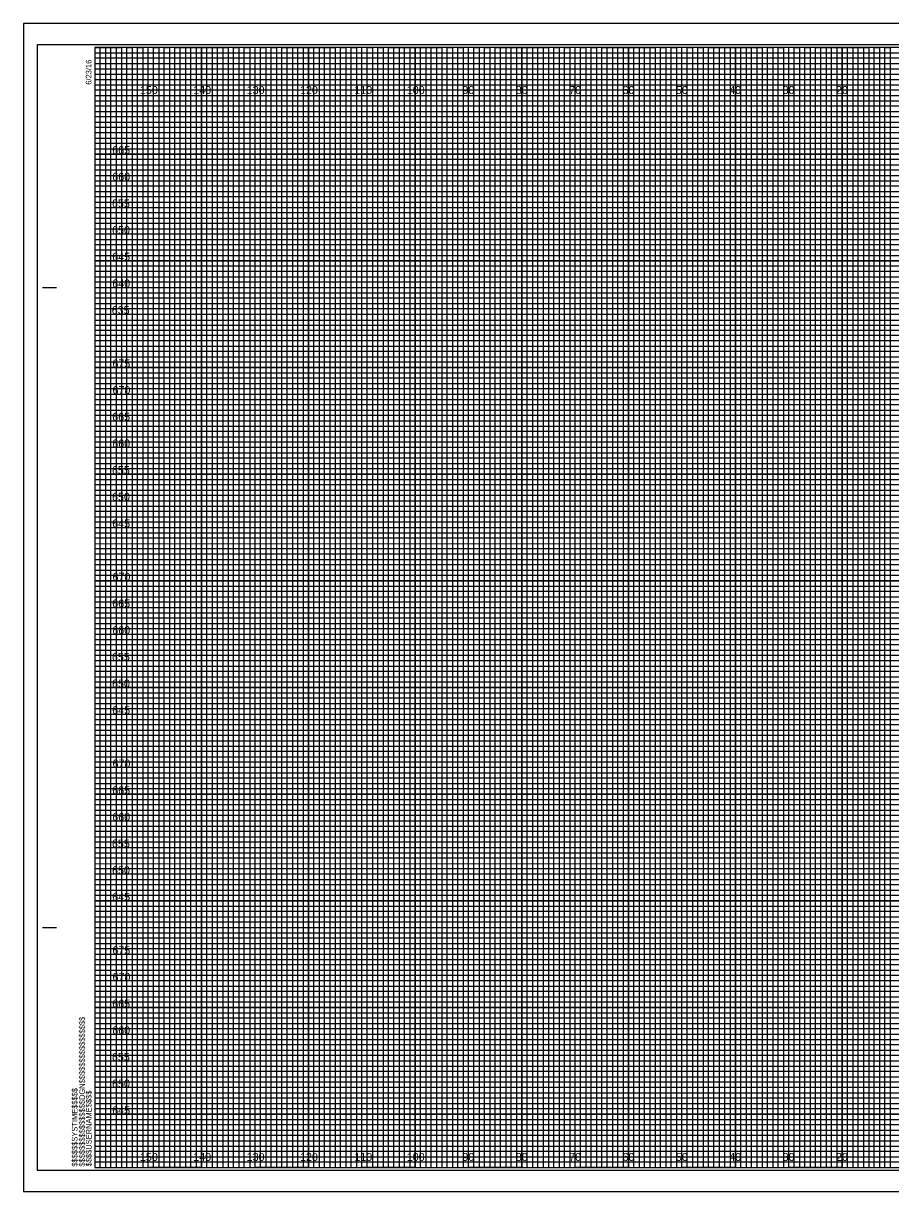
# Model space of a CAD drawing. Extents: x -13 to 323, y 215 to 434.
# Drawn here: x -13.4 to 149.1, y 215.5 to 434.5 of the extents above; entities that cross this region are included whole.
import ezdxf

# ---------------------------------------------------------------- set-up
doc = ezdxf.new("R2010")
doc.units = 0
for name, color, linetype in [('Exist Cross Section Cell', 7, 'Continuous'), ('Exist XS Center Line Elevation Label', 7, 'Continuous'), ('Exist XS Ground Line', 7, 'Continuous'), ('Prop XS Ditch Slope Text', 7, 'Continuous'), ('Prop XS Dump Level', 7, 'Continuous'), ('Prop XS Finish Grade', 7, 'Continuous'), ('Prop XS Finish Grade Earthwork', 7, 'Continuous'), ('Prop XS SE Text', 7, 'Continuous'), ('Prop XS Side Slope Text', 7, 'Continuous'), ('Prop XS SS Elevation Text', 7, 'Continuous'), ('Scratch_Level_3', 7, 'Continuous')]:
    doc.layers.add(name, color=color, linetype=linetype)

msp = doc.modelspace()

# ---------------------------------------------------------------- linework, layer by layer
at = {"layer": 'Exist Cross Section Cell'}
for points in [[(0, 430), (5, 430), (5, 220), (15, 220), (15, 430), (25, 430), (25, 220), (35, 220), (35, 430), (45, 430), (45, 220), (55, 220), (55, 430), (65, 430), (65, 220), (75, 220), (75, 430), (85, 430), (85, 220), (95, 220), (95, 430), (105, 430), (105, 220), (115, 220), (115, 430), (125, 430), (125, 220), (135, 220), (135, 430), (145, 430), (145, 220), (155, 220)], [(0, 425), (275, 425)], [(0, 405), (320, 405), (320, 415), (0, 415)], [(0, 385), (320, 385), (320, 395), (0, 395)], [(0, 365), (320, 365), (320, 375), (0, 375)], [(0, 345), (320, 345), (320, 355), (0, 355)], [(0, 325), (320, 325), (320, 335), (0, 335)], [(0, 305), (320, 305), (320, 315), (0, 315)], [(0, 285), (320, 285), (320, 295), (0, 295)], [(0, 265), (320, 265), (320, 275), (0, 275)], [(0, 245), (320, 245), (320, 255), (0, 255)], [(0, 225), (320, 225), (320, 235), (0, 235)]]:
    msp.add_lwpolyline(points, dxfattribs=at)
at = {"layer": 'Exist XS Center Line Elevation Label'}
for p, q in [((10, 430), (0, 430)), ((10, 220), (10, 430)), ((30, 430), (20, 430)), ((20, 430), (20, 220)), ((30, 220), (30, 430)), ((50, 430), (40, 430)), ((40, 430), (40, 220)), ((50, 220), (50, 430)), ((70, 430), (60, 430)), ((60, 430), (60, 220)), ((70, 220), (70, 430)), ((90, 430), (80, 430)), ((80, 430), (80, 220)), ((90, 220), (90, 430)), ((110, 430), (100, 430)), ((100, 430), (100, 220)), ((110, 220), (110, 430)), ((130, 430), (120, 430)), ((120, 430), (120, 220)), ((130, 220), (130, 430)), ((150, 430), (140, 430)), ((140, 430), (140, 220)), ((20, 220), (10, 220)), ((40, 220), (30, 220)), ((60, 220), (50, 220)), ((80, 220), (70, 220)), ((100, 220), (90, 220)), ((120, 220), (110, 220)), ((140, 220), (130, 220))]:
    msp.add_line(p, q, dxfattribs=at)
for points in [[(0, 420), (320, 420), (320, 410), (0, 410)], [(0, 400), (320, 400), (320, 390), (0, 390)], [(0, 380), (320, 380), (320, 370), (0, 370)], [(0, 360), (320, 360), (320, 350), (0, 350)], [(0, 340), (320, 340), (320, 330), (0, 330)], [(0, 320), (320, 320), (320, 310), (0, 310)], [(0, 300), (320, 300), (320, 290), (0, 290)], [(0, 280), (320, 280), (320, 270), (0, 270)], [(0, 260), (320, 260), (320, 250), (0, 250)], [(0, 240), (320, 240), (320, 230), (0, 230)]]:
    msp.add_lwpolyline(points, dxfattribs=at)
at = {"layer": 'Prop XS Ditch Slope Text'}
msp.add_lwpolyline([(-13.4, 215.5), (323.3, 215.5), (323.3, 434.5), (-13.4, 434.5)], close=True, dxfattribs=at)
at = {"layer": 'Prop XS Dump Level'}
for p, q in [((-9.8, 385), (-7.3, 385)), ((-9.7, 385), (-7.2, 385)), ((-9.8, 265), (-7.3, 265)), ((-9.7, 265), (-7.2, 265)), ((0, 220), (0, 220)), ((0, 220), (0, 220)), ((0, 220), (0, 220)), ((0, 220), (0, 220)), ((0, 220), (0, 220)), ((0, 220), (0, 220)), ((0, 220), (0, 220))]:
    msp.add_line(p, q, dxfattribs=at)
msp.add_lwpolyline([(320, 430), (0, 430), (0, 220), (320, 220)], close=True, dxfattribs=at)
at = {"layer": 'Prop XS Finish Grade Earthwork'}
for p, q in [((323.3, 434.5), (-13.4, 434.5)), ((-13.4, 434.5), (-13.4, 215.5)), ((-13.4, 215.5), (323.3, 215.5))]:
    msp.add_line(p, q, dxfattribs=at)
at = {"layer": 'Prop XS SE Text'}
for points in [[(0, 220), (1, 220), (1, 430), (2, 430), (2, 220)], [(2, 220), (3, 220), (3, 430), (4, 430), (4, 220)], [(5, 220), (6, 220), (6, 430), (7, 430), (7, 220)], [(7, 220), (8, 220), (8, 430), (9, 430), (9, 220)], [(10, 220), (11, 220), (11, 430), (12, 430), (12, 220)], [(12, 220), (13, 220), (13, 430), (14, 430), (14, 220)], [(15, 220), (16, 220), (16, 430), (17, 430), (17, 220)], [(17, 220), (18, 220), (18, 430), (19, 430), (19, 220)], [(20, 220), (21, 220), (21, 430), (22, 430), (22, 220)], [(22, 220), (23, 220), (23, 430), (24, 430), (24, 220)], [(25, 220), (26, 220), (26, 430), (27, 430), (27, 220)], [(27, 220), (28, 220), (28, 430), (29, 430), (29, 220)], [(30, 220), (31, 220), (31, 430), (32, 430), (32, 220)], [(32, 220), (33, 220), (33, 430), (34, 430), (34, 220)], [(35, 220), (36, 220), (36, 430), (37, 430), (37, 220)], [(37, 220), (38, 220), (38, 430), (39, 430), (39, 220)], [(40, 220), (41, 220), (41, 430), (42, 430), (42, 220)], [(42, 220), (43, 220), (43, 430), (44, 430), (44, 220)], [(45, 220), (46, 220), (46, 430), (47, 430), (47, 220)], [(47, 220), (48, 220), (48, 430), (49, 430), (49, 220)], [(50, 220), (51, 220), (51, 430), (52, 430), (52, 220)], [(52, 220), (53, 220), (53, 430), (54, 430), (54, 220)], [(55, 220), (56, 220), (56, 430), (57, 430), (57, 220)], [(57, 220), (58, 220), (58, 430), (59, 430), (59, 220)], [(60, 220), (61, 220), (61, 430), (62, 430), (62, 220)], [(62, 220), (63, 220), (63, 430), (64, 430), (64, 220)], [(65, 220), (66, 220), (66, 430), (67, 430), (67, 220)], [(67, 220), (68, 220), (68, 430), (69, 430), (69, 220)], [(70, 220), (71, 220), (71, 430), (72, 430), (72, 220)], [(72, 220), (73, 220), (73, 430), (74, 430), (74, 220)], [(75, 220), (76, 220), (76, 430), (77, 430), (77, 220)], [(77, 220), (78, 220), (78, 430), (79, 430), (79, 220)], [(80, 220), (81, 220), (81, 430), (82, 430), (82, 220)], [(82, 220), (83, 220), (83, 430), (84, 430), (84, 220)], [(85, 220), (86, 220), (86, 430), (87, 430), (87, 220)], [(87, 220), (88, 220), (88, 430), (89, 430), (89, 220)], [(90, 220), (91, 220), (91, 430), (92, 430), (92, 220)], [(92, 220), (93, 220), (93, 430), (94, 430), (94, 220)], [(95, 220), (96, 220), (96, 430), (97, 430), (97, 220)], [(97, 220), (98, 220), (98, 430), (99, 430), (99, 220)], [(100, 220), (101, 220), (101, 430), (102, 430), (102, 220)], [(102, 220), (103, 220), (103, 430), (104, 430), (104, 220)], [(105, 220), (106, 220), (106, 430), (107, 430), (107, 220)], [(107, 220), (108, 220), (108, 430), (109, 430), (109, 220)], [(110, 220), (111, 220), (111, 430), (112, 430), (112, 220)], [(112, 220), (113, 220), (113, 430), (114, 430), (114, 220)], [(115, 220), (116, 220), (116, 430), (117, 430), (117, 220)], [(117, 220), (118, 220), (118, 430), (119, 430), (119, 220)], [(120, 220), (121, 220), (121, 430), (122, 430), (122, 220)], [(122, 220), (123, 220), (123, 430), (124, 430), (124, 220)], [(125, 220), (126, 220), (126, 430), (127, 430), (127, 220)], [(127, 220), (128, 220), (128, 430), (129, 430), (129, 220)], [(130, 220), (131, 220), (131, 430), (132, 430), (132, 220)], [(132, 220), (133, 220), (133, 430), (134, 430), (134, 220)], [(135, 220), (136, 220), (136, 430), (137, 430), (137, 220)], [(137, 220), (138, 220), (138, 430), (139, 430), (139, 220)], [(140, 220), (141, 220), (141, 430), (142, 430), (142, 220)], [(142, 220), (143, 220), (143, 430), (144, 430), (144, 220)], [(145, 220), (146, 220), (146, 430), (147, 430), (147, 220)], [(147, 220), (148, 220), (148, 430), (149, 430), (149, 220)]]:
    msp.add_lwpolyline(points, dxfattribs=at)
at = {"layer": 'Prop XS Side Slope Text'}
msp.add_lwpolyline([(-10.8, 219.5), (322.4, 219.5), (322.4, 430.5), (-10.8, 430.5)], close=True, dxfattribs=at)
at = {"layer": 'Prop XS SS Elevation Text'}
for p, q in [((10, 220), (10, 430)), ((20, 220), (20, 430)), ((30, 220), (30, 430)), ((40, 220), (40, 430)), ((50, 220), (50, 430)), ((60, 220), (60, 430)), ((70, 220), (70, 430)), ((80, 220), (80, 430)), ((90, 220), (90, 430)), ((100, 220), (100, 430)), ((110, 220), (110, 430)), ((120, 220), (120, 430)), ((130, 220), (130, 430)), ((140, 220), (140, 430)), ((0, 420), (320, 420)), ((0, 410), (320, 410)), ((0, 400), (320, 400)), ((0, 390), (320, 390)), ((0, 380), (320, 380)), ((0, 370), (320, 370)), ((0, 360), (320, 360)), ((0, 350), (320, 350)), ((0, 340), (320, 340)), ((0, 330), (320, 330)), ((0, 320), (320, 320)), ((0, 310), (320, 310)), ((0, 300), (320, 300)), ((0, 290), (320, 290)), ((0, 280), (320, 280)), ((0, 270), (320, 270)), ((0, 260), (320, 260)), ((0, 250), (320, 250)), ((0, 240), (320, 240)), ((0, 230), (320, 230))]:
    msp.add_line(p, q, dxfattribs=at)
at = {"layer": 'Scratch_Level_3'}
for p, q in [((0, 429), (260, 429)), ((260, 427.98), (0, 427.98)), ((0, 427.98), (0, 427)), ((0, 427), (260, 427)), ((260, 425.89), (0, 425.89)), ((0, 425.89), (0, 424)), ((0, 424), (320, 424))]:
    msp.add_line(p, q, dxfattribs=at)
for points in [[(0, 423), (270, 423), (320, 423), (320, 422), (0, 422)], [(0, 421), (320, 421), (320, 419), (0, 419)], [(0, 418), (320, 418), (320, 417), (0, 416.98)], [(0, 416), (320, 416), (320, 414), (0, 414)], [(0, 413), (320, 413), (320, 412), (0, 412)], [(0, 411), (320, 411), (320, 409), (0, 409)], [(0, 408), (320, 408), (320, 407), (0, 407)], [(0, 406), (320, 406), (320, 404), (0, 404)], [(0, 403), (320, 403), (320, 402), (0, 402)], [(0, 401), (320, 401), (320, 399), (0, 399)], [(0, 398), (320, 398), (320, 397), (0, 397)], [(0, 396), (320, 396), (320, 393.95), (320, 393), (320, 392), (0, 392)], [(0, 394), (320, 394), (320, 393), (0, 393)], [(0, 391), (320, 391), (320, 389), (0, 389.03)], [(0, 389.03), (320, 389), (320, 388), (0, 388)], [(0, 387), (320, 387), (320, 386), (0, 386)], [(0, 384), (320, 384), (320, 383), (0, 383)], [(0, 382), (320, 382), (320, 381), (0, 381)], [(-0.07, 378.89), (320, 378.89), (320, 377.88), (-0.07, 377.88)], [(0, 377), (320, 377), (320, 376), (0, 376)], [(0, 374), (320, 374), (320, 373), (0, 373)], [(0, 372), (320, 372), (320, 371), (0, 371)], [(0, 369), (320, 369), (320, 368), (0, 368)], [(0, 367), (320, 367), (320, 366), (0, 366)], [(0, 364), (320, 364), (320, 363), (0, 363)], [(0, 362), (320, 362), (320, 361), (0, 361)], [(0, 359), (320, 359), (319.99, 357.98), (0, 358)], [(0, 357), (320, 357), (320, 356), (0, 356)], [(0, 354), (320, 354), (320, 353), (0, 353)], [(0, 352), (320, 352), (320, 351), (0, 351)], [(0, 349), (320, 349), (320, 348), (0, 348)], [(0, 347), (320, 347), (320, 346), (0, 346)], [(0, 344), (320, 344), (320, 343), (0, 343)], [(0, 342), (320, 342), (320, 341), (0, 341)], [(0, 339), (320, 339), (320, 338), (0, 338)], [(0, 336.99), (320.07, 336.91), (320, 336), (0, 336)], [(0, 334), (320, 334), (320, 333), (0, 333)], [(0, 332), (320, 332), (320, 331), (0, 331)], [(0, 329), (320, 329), (320, 328), (0, 328)], [(0, 327), (320, 327), (320, 326), (0, 326)], [(0, 324), (320, 324), (320, 323), (0, 323)], [(0, 322), (320, 322), (320, 321), (0, 321)], [(0, 319), (320, 319), (320, 318), (0, 318)], [(0, 317), (320, 317), (320, 316), (0, 316)], [(0, 314), (320, 314), (320, 313), (0, 313)], [(0, 312), (320, 312), (320, 311), (0, 311)], [(0, 309), (320, 309), (320, 308), (0, 308)], [(0, 307), (320, 307), (320, 306), (0, 306)], [(0, 304), (320, 304), (320, 303), (0, 303)], [(0, 302), (320, 302), (320, 301), (0, 301)], [(0, 299), (320, 299), (319.99, 297.98), (0, 298)], [(0, 297), (320, 297), (320, 296), (0, 296)], [(0, 294), (320, 294), (320, 293), (0, 293)], [(0, 292), (320, 292), (320, 291), (0, 291)], [(0, 289), (320, 289), (320, 288), (0, 288)], [(0, 287), (320, 287), (320, 286), (0, 286)], [(0, 284), (320, 284), (320, 283), (0, 283)], [(0, 282), (320, 282), (320, 281), (0, 281)], [(0, 279), (320, 279), (320, 278), (0, 278)], [(0, 276.99), (320.07, 276.91), (320, 276), (0, 276)], [(0, 274), (320, 274), (320, 273), (0, 273)], [(0, 272), (320, 272), (320, 271), (0, 271)], [(0, 269), (320, 269), (320, 268), (0, 268)], [(0, 267), (320, 267), (320, 266), (0, 266)], [(0, 264), (320, 264), (320, 263), (0, 263)], [(0, 262), (320, 262), (320, 261), (0, 261)], [(0, 259), (320, 259), (320, 258), (0, 258)], [(0, 257), (320, 257), (320, 256), (0, 256)], [(0, 254), (320, 254), (320, 253), (0, 253)], [(0, 252), (320, 252), (320, 251), (0, 251)], [(0, 249), (320, 249), (320, 248), (0, 248)], [(0, 247), (320, 247), (320, 246), (0, 246)], [(0, 244), (320, 244), (320, 243), (0, 243)], [(0, 242), (320, 242), (320, 241), (0, 241)], [(0, 239), (320, 239), (320, 238), (0, 238)], [(0, 237), (320, 237), (320, 236), (0, 236)], [(0, 234), (320, 234), (320, 233), (0, 233)], [(0, 232), (320, 232), (320, 231), (0, 231)], [(0, 229), (320, 229), (320, 228), (0, 228)], [(0, 227), (320, 227), (320, 226), (0, 226)], [(0, 224), (320, 224), (320, 223), (0, 223)], [(0, 222), (320, 222), (320, 221), (0, 221)]]:
    msp.add_lwpolyline(points, dxfattribs=at)

# ---------------------------------------------------------------- texts
at = {"layer": 'Exist XS Ground Line'}
for s, p in [('150', (8.44, 421.25)), ('140', (18.44, 421.25)), ('130', (28.44, 421.25)), ('120', (38.44, 421.25)), ('110', (48.62, 421.25)), ('100', (58.44, 421.25)), ('90', (68.86, 421.25)), ('80', (78.86, 421.25)), ('70', (88.86, 421.25)), ('60', (98.86, 421.25)), ('50', (108.86, 421.25)), ('40', (118.86, 421.25)), ('30', (128.86, 421.25)), ('20', (138.86, 421.25)), ('150', (8.44, 221.25)), ('140', (18.44, 221.25)), ('130', (28.44, 221.25)), ('120', (38.44, 221.25)), ('110', (48.62, 221.25)), ('100', (58.44, 221.25)), ('90', (68.86, 221.25)), ('80', (78.86, 221.25)), ('70', (88.86, 221.25)), ('60', (98.86, 221.25)), ('50', (108.86, 221.25)), ('40', (118.86, 221.25)), ('30', (128.86, 221.25)), ('20', (138.86, 221.25))]:
    msp.add_text(s, height=1.5, dxfattribs=at).set_placement(p)
at = {"layer": 'Prop XS Dump Level'}
for s, p in [('6/23/16', (-0.65, 423)), ('$$$$$$$$$$$$$$$$DGN$$$$$$$$$$$$$$$$', (-1.88, 220.18)), ('$$$$$$SYSTIME$$$$$', (-3.26, 220.18)), ('$$$$USERNAME$$$$', (-0.62, 220.23))]:
    msp.add_text(s, height=1.05, rotation=90, dxfattribs=at).set_placement(p)
at = {"layer": 'Prop XS Finish Grade'}
for s, p in [('665', (3.25, 410)), ('660', (3.26, 405)), ('655', (3.2, 400)), ('650', (3.22, 395)), ('645', (3.25, 390)), ('640', (3.26, 385)), ('635', (3.16, 380)), ('675', (3.28, 370)), ('670', (3.3, 365)), ('665', (3.25, 360)), ('660', (3.26, 355)), ('655', (3.2, 350)), ('650', (3.22, 345)), ('645', (3.25, 340)), ('670', (3.3, 330)), ('665', (3.25, 325)), ('660', (3.26, 320)), ('655', (3.2, 315)), ('650', (3.22, 310)), ('645', (3.25, 305)), ('670', (3.3, 295)), ('665', (3.25, 290)), ('660', (3.26, 285)), ('655', (3.2, 280)), ('650', (3.22, 275)), ('645', (3.25, 270)), ('675', (3.28, 260)), ('670', (3.3, 255)), ('665', (3.25, 250)), ('660', (3.26, 245)), ('655', (3.2, 240)), ('650', (3.22, 235)), ('645', (3.25, 230))]:
    msp.add_text(s, height=1.5, dxfattribs=at).set_placement(p)

doc.saveas('drawing.dxf')
